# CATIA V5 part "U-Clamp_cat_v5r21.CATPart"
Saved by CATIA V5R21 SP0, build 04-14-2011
Part number: U-Clamp
Bounding box of the stored display mesh (mm): x -23 to 23, y -6.5 to 6.5, z -25 to 29
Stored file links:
  D:\CATIA V5R21 E-RESOURCES\CATIA-V5R21\catia-v5r21-Tut\c14-catia-v5r21-tut\c14-catia-v5r21-tut02\Part & Asm files\U-Clamp_cat_v5r21.CATPart
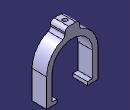
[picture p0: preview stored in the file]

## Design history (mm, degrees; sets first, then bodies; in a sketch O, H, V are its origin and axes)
Body1 (main body)
  Sketch1 on zx-plane, origin (0, 0, 0), H (-1, 0, 0), V (0, 0, 1)
    arc A1 centre (0, 0) radius 18 from (18, 0) to (-18, 0) ccw
    point P1 (-18, 0)
    point P2 (18, 0)
    line L1 (-18, 0) -> (-18, -22)
    point P3 (-18, -22)
    line L2 (-18, -22) -> (-13.5, -22)
    point P4 (-13.5, -22)
    line L3 (-13.5, -22) -> (-13.5, -25)
    point P5 (-13.5, -25)
    line L4 (-13.5, -25) -> (-23, -25)
    point P6 (-23, -25)
    line L5 (-23, -25) -> (-23, 0)
    point P7 (-23, 0)
    arc A2 centre (0, 0) radius 23 from (-23, 0) to (-6.5, 22.0624) cw
    point P9 (23, 0)
    point P10 (23, 0)
    point P11 (23, -25)
    line L6 (23, -25) -> (23, 0)
    point P12 (13.5, -25)
    line L7 (13.5, -25) -> (23, -25)
    point P13 (13.5, -22)
    line L8 (13.5, -22) -> (13.5, -25)
    point P14 (18, -22)
    line L9 (18, -22) -> (13.5, -22)
    point P15 (18, 0)
    line L10 (18, 0) -> (18, -22)
    line L11 (-6.5, 22.0624) -> (-6.5, 29)
    point P16 (-6.5, 29)
    line L12 (-6.5, 29) -> (6.5, 29)
    point P17 (6.5, 29)
    line L13 (6.5, 29) -> (6.5, 22.0624)
    point P18 (6.5, 22.0624)
    arc A3 centre (0, 0) radius 23 from (6.5, 22.0624) to (23, 0) cw
    distance L3 V = 13.5
    distance H L4 = 25
    distance V L5 = 23
    distance P16 P17 = 13
    distance L11 V = 6.5
    distance L7 L12 = 54
    distance L1 L5 = 5
    length L3 = 3
    coincidence: P1 H, P2 H, P7 H, A2 P18, A2 A3, P2 P15, P9 P10
    tangency: L1 A1, A2 L5
    horizontal: L2 H, L4 H, L12 H
    vertical: L3 V, L5 V, L11 V, L13 V
    concentricity: A2 A1
    symmetry: P7 P10 V, P6 P11 V, L5 L6 V, P5 P12 V, L4 L7 V, P4 P13 V, L3 L8 V, P3 P14 V, L2 L9 V, P1 P15 V, L1 L10 V
  Pad1: profile Sketch1, direction (0, -1, 0), length 6.5, mirrored extent
  Fillet1: radius 3.302, on 4 edges
  Sketch2 on face of Pad1, origin (-0.057, 2.6412, 29), H (1, 0, 0), V (0, 1, 0)
    point P1 (0.057, -2.6412)
    reference intersected line E1 through (0.057, 0) direction (0, 1) from yz-plane
    reference intersected line E2 through (0, -2.6412) direction (-1, 0) from zx-plane
    coincidence: E1 P1, E2 P1
  Hole1: placed by Sketch2, at (0, 0, 29) direction (0, 0, -1), diameter 4, depth 25.4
